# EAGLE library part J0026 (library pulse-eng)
RJ45 PulseJack w/LEDs
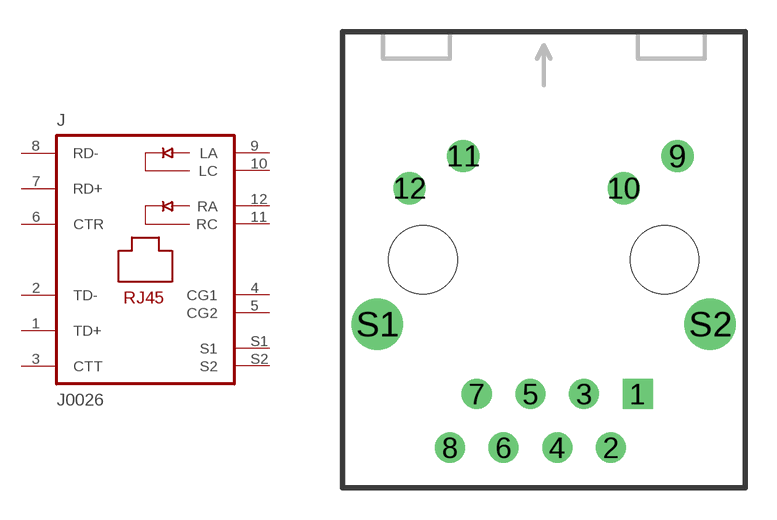
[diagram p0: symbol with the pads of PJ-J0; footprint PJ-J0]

Designator prefix J

## J0026  [PJ-J0]
1  TD+
2  TD-
3  CTT
4  CG1  pas
5  CG2  pas
6  CTR
7  RD+
8  RD-
9  LA  pas
10  LC  pas
11  RC  pas
12  RA  pas
S1  S1  pas
S2  S2  pas

## Footprint PJ-J0 (pad centres in mm)
RJ45 with Ethernet Balun and LED's
drill 0.914 square: 1 4.445,-6.35
drill 0.914 round: 2 3.175,-8.89; 3 1.905,-6.35; 4 0.635,-8.89; 5 -0.635,-6.35; 6 -1.905,-8.89; 7 -3.175,-6.35; 8 -4.445,-8.89
drill 1.016 round: 9 6.325,4.902; 10 3.785,3.378; 11 -3.81,4.902; 12 -6.35,3.378
drill 1.626 round: S1 -7.874,-3.048; S2 7.874,-3.048
hole 3.251 at -5.715,0
hole 3.251 at 5.715,0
